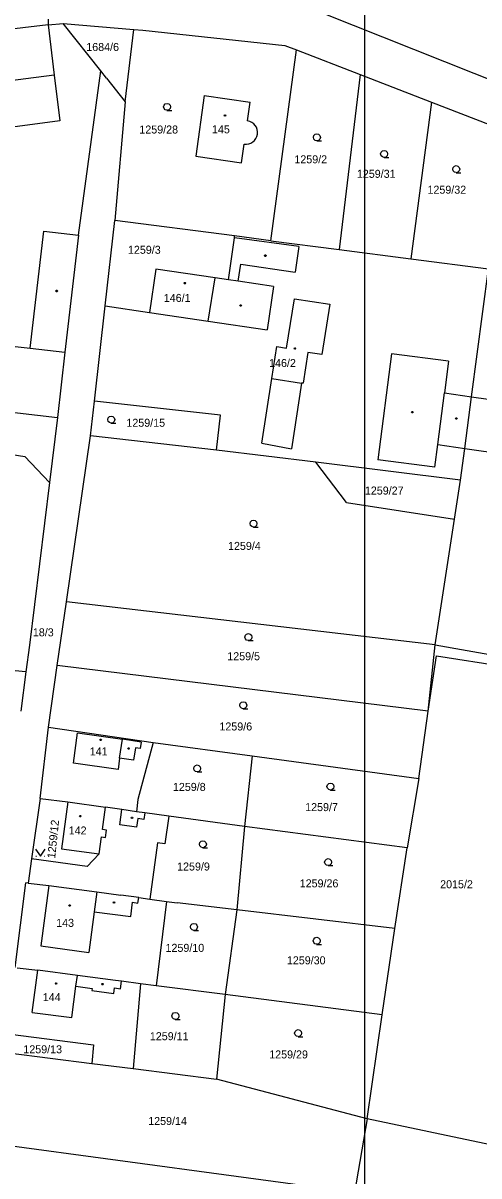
# Model space of a CAD drawing. Extents: x -802857 to -799647, y -1020285 to -1015884.
# Drawn here: x -801322.5 to -801225.7, y -1017885.2 to -1017640.2 of the extents above; entities that cross this region are included whole.
import ezdxf

# ---------------------------------------------------------------- set-up
doc = ezdxf.new("R2010")
doc.units = 0
for name, color, linetype in [('Default', 7, 'Continuous'), ('KLADY_ZMVM', 7, 'Continuous'), ('KN_HRANICE', 7, 'Continuous'), ('KN_KULTURY', 7, 'Continuous'), ('KN_PARCELY', 7, 'Continuous'), ('KN_SLUCKY', 7, 'Continuous')]:
    doc.layers.add(name, color=color, linetype=linetype)

# ---------------------------------------------------------------- blocks, each defined once
blk = doc.blocks.new('304')
at = {"layer": 'Default'}
blk.add_lwpolyline([(0, 0), (-0.38, 0.1), (-0.65, 0.37), (-0.75, 0.74), (-0.65, 1.11), (-0.38, 1.38), (-0.01, 1.48), (0.36, 1.38), (0.63, 1.11), (0.73, 0.73), (0.63, 0.35), (0.36, 0.08), (-0.02, -0.02), (0.98, -0.02)], dxfattribs=at)
blk = doc.blocks.new('314')
at = {"layer": 'Default'}
for p, q in [((-0.95, 0), (-0.85, 0)), ((0.85, 0), (0.95, 0))]:
    blk.add_line(p, q, dxfattribs=at)
blk.add_lwpolyline([(-1, 1.5), (0, 0), (1, 1.5)], dxfattribs=at)
blk = doc.blocks.new('402')
at = {"layer": 'Default'}
blk.add_lwpolyline([(0.09, 0.15), (0.18, 0), (0.09, -0.15), (-0.09, -0.15), (-0.18, 0), (-0.09, 0.15), (0.09, 0.15)], dxfattribs=at)

msp = doc.modelspace()

# ---------------------------------------------------------------- linework, layer by layer
at = {"layer": 'KLADY_ZMVM'}
msp.add_lwpolyline([(-801250, -1017000), (-801250, -1017500), (-801250, -1018000)], dxfattribs=at)
at = {"layer": 'KN_HRANICE'}
for p, q in [((-801258.97, -1017638.08), (-801218.75, -1017654.12)), ((-801317.19, -1017639.44), (-801317.18, -1017640.62)), ((-801317.18, -1017640.62), (-801313.96, -1017640.33)), ((-801317.18, -1017640.62), (-801315.88, -1017651.33)), ((-801313.96, -1017640.33), (-801298.97, -1017641.6)), ((-801306.02, -1017650.39), (-801313.96, -1017640.33)), ((-801300.81, -1017657), (-801298.97, -1017641.6)), ((-801298.97, -1017641.6), (-801297.08, -1017641.76)), ((-801297.08, -1017641.76), (-801266.9, -1017645.01)), ((-801269.88, -1017686.48), (-801264.46, -1017645.95)), ((-801266.9, -1017645.01), (-801264.46, -1017645.95)), ((-801264.46, -1017645.95), (-801250.95, -1017651.18)), ((-801310.75, -1017685.3), (-801306.02, -1017650.39)), ((-801304.78, -1017651.96), (-801306.02, -1017650.39)), ((-801250.95, -1017651.18), (-801255.36, -1017688.35)), ((-801250.95, -1017651.18), (-801235.81, -1017657.04)), ((-801315.88, -1017651.33), (-801314.72, -1017661.03)), ((-801304.78, -1017651.96), (-801300.81, -1017657)), ((-801284.03, -1017655.6), (-801285.84, -1017668.53)), ((-801284.03, -1017655.6), (-801274.3, -1017657.02)), ((-801300.81, -1017657), (-801303.02, -1017682.18)), ((-801274.86, -1017661.01), (-801274.3, -1017657.02)), ((-801235.81, -1017657.04), (-801240.18, -1017690.3)), ((-801235.81, -1017657.04), (-801220.05, -1017663.14)), ((-801314.72, -1017661.03), (-801346.31, -1017665.23)), ((-801276.11, -1017669.95), (-801275.55, -1017665.96)), ((-801285.84, -1017668.53), (-801276.11, -1017669.95)), ((-801305.07, -1017700.32), (-801303.02, -1017682.18)), ((-801277.57, -1017685.48), (-801303.02, -1017682.18)), ((-801310.75, -1017685.3), (-801313.62, -1017710.16)), ((-801278.9, -1017694.79), (-801277.62, -1017685.88)), ((-801277.62, -1017685.88), (-801277.57, -1017685.48)), ((-801269.88, -1017686.48), (-801277.57, -1017685.48)), ((-801269.88, -1017686.48), (-801255.36, -1017688.35)), ((-801255.36, -1017688.35), (-801240.18, -1017690.3)), ((-801240.18, -1017690.3), (-801223.64, -1017692.43)), ((-801294.28, -1017692.51), (-801295.64, -1017701.71)), ((-801281.73, -1017694.37), (-801294.28, -1017692.51)), ((-801227.27, -1017719.62), (-801223.64, -1017692.43)), ((-801278.9, -1017694.79), (-801281.73, -1017694.37)), ((-801266.53, -1017709.31), (-801264.9, -1017698.8)), ((-801264.9, -1017698.8), (-801257.36, -1017699.97)), ((-801257.36, -1017699.97), (-801259.03, -1017710.68)), ((-801307.35, -1017720.56), (-801305.07, -1017700.32)), ((-801305.07, -1017700.32), (-801295.64, -1017701.71)), ((-801269.68, -1017715.75), (-801268.63, -1017708.99)), ((-801268.63, -1017708.99), (-801266.53, -1017709.31)), ((-801313.62, -1017710.16), (-801315.22, -1017724.02)), ((-801262.01, -1017710.22), (-801263.03, -1017716.78)), ((-801259.03, -1017710.68), (-801262.01, -1017710.22)), ((-801271.82, -1017729.5), (-801269.68, -1017715.75)), ((-801263.35, -1017716.73), (-801265.52, -1017730.72)), ((-801263.03, -1017716.78), (-801263.35, -1017716.73)), ((-801360.4, -1017718.86), (-801315.22, -1017724.02)), ((-801228.73, -1017730.61), (-801227.27, -1017719.62)), ((-801308.18, -1017727.92), (-801307.35, -1017720.56)), ((-801280.57, -1017723.56), (-801307.35, -1017720.56)), ((-801315.22, -1017724.02), (-801316.92, -1017737.87)), ((-801281.41, -1017730.95), (-801280.57, -1017723.56)), ((-801313.28, -1017763.19), (-801308.18, -1017727.92)), ((-801281.41, -1017730.95), (-801308.18, -1017727.92)), ((-801271.82, -1017729.5), (-801265.52, -1017730.72)), ((-801330.53, -1017731.02), (-801322.14, -1017732.32)), ((-801260.34, -1017733.55), (-801281.41, -1017730.95)), ((-801229.63, -1017737.33), (-801228.73, -1017730.61)), ((-801322.14, -1017732.32), (-801316.92, -1017737.87)), ((-801253.83, -1017742.07), (-801260.34, -1017733.55)), ((-801229.63, -1017737.33), (-801260.34, -1017733.55)), ((-801316.92, -1017737.87), (-801321.16, -1017772.38)), ((-801230.91, -1017745.67), (-801229.63, -1017737.33)), ((-801253.83, -1017742.07), (-801230.91, -1017745.67)), ((-801234.99, -1017772.37), (-801230.91, -1017745.67)), ((-801315.24, -1017776.75), (-801313.28, -1017763.19)), ((-801234.99, -1017772.37), (-801313.28, -1017763.19)), ((-801321.16, -1017772.38), (-801321.89, -1017778.08)), ((-801236.48, -1017786.43), (-801234.99, -1017772.37)), ((-801234.99, -1017772.37), (-801172.15, -1017783.49)), ((-801236.48, -1017786.43), (-801234.69, -1017774.68)), ((-801234.69, -1017774.68), (-801206.04, -1017779.14)), ((-801321.89, -1017778.08), (-801333.83, -1017776.95)), ((-801321.89, -1017778.08), (-801322.97, -1017786.42)), ((-801317.13, -1017789.83), (-801315.24, -1017776.75)), ((-801236.48, -1017786.43), (-801315.24, -1017776.75)), ((-801238.47, -1017800.75), (-801236.48, -1017786.43)), ((-801318.85, -1017804.96), (-801317.13, -1017789.83)), ((-801317.13, -1017789.83), (-801294.9, -1017793.05)), ((-801294.9, -1017793.05), (-801298.1, -1017805.2)), ((-801294.9, -1017793.05), (-801273.85, -1017795.89)), ((-801273.85, -1017795.89), (-801275.49, -1017810.94)), ((-801273.85, -1017795.89), (-801238.47, -1017800.75)), ((-801238.47, -1017800.75), (-801240.97, -1017815.46)), ((-801318.85, -1017804.96), (-801320.69, -1017817.83)), ((-801318.85, -1017804.96), (-801313, -1017805.71)), ((-801298.1, -1017805.2), (-801298.41, -1017807.79)), ((-801313, -1017805.71), (-801314.37, -1017815.67)), ((-801313, -1017805.71), (-801305, -1017806.85)), ((-801301.51, -1017807.35), (-801305, -1017806.85)), ((-801298.41, -1017807.79), (-801301.51, -1017807.35)), ((-801296.65, -1017808.02), (-801298.41, -1017807.79)), ((-801291.57, -1017808.72), (-801296.65, -1017808.02)), ((-801291.57, -1017808.72), (-801292.38, -1017814.62)), ((-801275.49, -1017810.94), (-801291.57, -1017808.72)), ((-801275.49, -1017810.94), (-801277.13, -1017828.65)), ((-801240.97, -1017815.46), (-801275.49, -1017810.94)), ((-801293.96, -1017814.4), (-801295.6, -1017826.35)), ((-801292.38, -1017814.62), (-801293.96, -1017814.4)), ((-801314.37, -1017815.67), (-801306.37, -1017816.77)), ((-801306.37, -1017816.77), (-801308.92, -1017819.41)), ((-801243.53, -1017832.62), (-801240.97, -1017815.46)), ((-801320.69, -1017817.83), (-801321.42, -1017822.98)), ((-801308.92, -1017819.41), (-801320.69, -1017817.83)), ((-801324.21, -1017840.9), (-801321.92, -1017822.92)), ((-801321.42, -1017822.98), (-801321.92, -1017822.92)), ((-801321.42, -1017822.98), (-801317, -1017823.5)), ((-801317, -1017823.5), (-801306.82, -1017824.84)), ((-801306.82, -1017824.84), (-801301.75, -1017825.51)), ((-801297.95, -1017826.03), (-801301.75, -1017825.51)), ((-801297.95, -1017826.03), (-801295.6, -1017826.35)), ((-801295.6, -1017826.35), (-801292.03, -1017826.83)), ((-801292.03, -1017826.83), (-801294.26, -1017844.75)), ((-801292.03, -1017826.83), (-801289.77, -1017827.14)), ((-801277.13, -1017828.65), (-801289.77, -1017827.14)), ((-801277.13, -1017828.65), (-801279.58, -1017846.65)), ((-801243.53, -1017832.62), (-801277.13, -1017828.65)), ((-801246.26, -1017850.96), (-801243.53, -1017832.62)), ((-801323.76, -1017840.95), (-801319.39, -1017841.48)), ((-801310.96, -1017842.58), (-801319.39, -1017841.48)), ((-801302.87, -1017843.64), (-801310.96, -1017842.58)), ((-801301.57, -1017843.81), (-801302.87, -1017843.64)), ((-801297.53, -1017844.33), (-801301.57, -1017843.81)), ((-801297.53, -1017844.33), (-801299.15, -1017862.36)), ((-801294.26, -1017844.75), (-801297.53, -1017844.33)), ((-801279.58, -1017846.65), (-801294.26, -1017844.75)), ((-801279.58, -1017846.65), (-801281.41, -1017864.6)), ((-801246.26, -1017850.96), (-801279.58, -1017846.65)), ((-801249.45, -1017873.01), (-801246.26, -1017850.96)), ((-801325.19, -1017855.03), (-801307.53, -1017857.34)), ((-801325.59, -1017859.01), (-801307.91, -1017861.25)), ((-801307.53, -1017857.34), (-801307.91, -1017861.25)), ((-801307.91, -1017861.25), (-801299.15, -1017862.36)), ((-801299.15, -1017862.36), (-801281.41, -1017864.6)), ((-801249.45, -1017873.01), (-801281.41, -1017864.6)), ((-801249.45, -1017873.01), (-801252.11, -1017888.65)), ((-801223.26, -1017878.53), (-801249.45, -1017873.01)), ((-801252.11, -1017888.65), (-801327.56, -1017878.51))]:
    msp.add_line(p, q, dxfattribs=at)
msp.add_arc((-801275.2, -1017663.49), 2.5, 262.0645, 82.0644, dxfattribs=at)
at = {"layer": 'KN_SLUCKY'}
for p, q in [((-801317.18, -1017640.62), (-801334.53, -1017642.7)), ((-801315.88, -1017651.33), (-801346.88, -1017655.22)), ((-801320.96, -1017709.32), (-801318.12, -1017684.46)), ((-801318.12, -1017684.46), (-801310.75, -1017685.3)), ((-801263.92, -1017687.68), (-801277.62, -1017685.88)), ((-801263.92, -1017687.68), (-801264.71, -1017693.15)), ((-801276.81, -1017695.1), (-801276.28, -1017691.44)), ((-801276.28, -1017691.44), (-801264.71, -1017693.15)), ((-801283.17, -1017703.56), (-801281.73, -1017694.37)), ((-801276.81, -1017695.1), (-801278.9, -1017694.79)), ((-801269.34, -1017696.2), (-801276.81, -1017695.1)), ((-801269.34, -1017696.2), (-801270.7, -1017705.4)), ((-801295.64, -1017701.71), (-801283.17, -1017703.56)), ((-801283.17, -1017703.56), (-801270.7, -1017705.4)), ((-801335.42, -1017707.67), (-801320.96, -1017709.32)), ((-801320.96, -1017709.32), (-801313.62, -1017710.16)), ((-801244.25, -1017710.49), (-801247.15, -1017733)), ((-801232.15, -1017712.05), (-801244.25, -1017710.49)), ((-801232.15, -1017712.05), (-801233.02, -1017718.8)), ((-801269.68, -1017715.75), (-801263.35, -1017716.73)), ((-801234.44, -1017729.8), (-801233.02, -1017718.8)), ((-801233.02, -1017718.8), (-801227.27, -1017719.62)), ((-801227.27, -1017719.62), (-801204.41, -1017722.86)), ((-801235.05, -1017734.56), (-801234.44, -1017729.8)), ((-801234.44, -1017729.8), (-801228.73, -1017730.61)), ((-801228.73, -1017730.61), (-801206.81, -1017733.72)), ((-801235.05, -1017734.56), (-801247.15, -1017733)), ((-801311.81, -1017797.47), (-801310.92, -1017791.04)), ((-801310.92, -1017791.04), (-801301.41, -1017792.41)), ((-801301.99, -1017796.42), (-801301.41, -1017792.41)), ((-801297.4, -1017792.99), (-801301.41, -1017792.41)), ((-801297.4, -1017792.99), (-801297.6, -1017794.37)), ((-801298.64, -1017794.22), (-801299.02, -1017796.85)), ((-801297.6, -1017794.37), (-801298.64, -1017794.22)), ((-801302.34, -1017798.84), (-801311.81, -1017797.47)), ((-801301.99, -1017796.42), (-801302.34, -1017798.84)), ((-801299.02, -1017796.85), (-801301.99, -1017796.42)), ((-801305.65, -1017811.57), (-801305, -1017806.85)), ((-801301.96, -1017810.55), (-801301.51, -1017807.35)), ((-801298.14, -1017809.22), (-801298.4, -1017811.06)), ((-801296.85, -1017809.41), (-801298.14, -1017809.22)), ((-801296.65, -1017808.02), (-801296.85, -1017809.41)), ((-801304.76, -1017811.69), (-801305.65, -1017811.57)), ((-801304.98, -1017813.28), (-801304.76, -1017811.69)), ((-801298.4, -1017811.06), (-801301.96, -1017810.55)), ((-801306.37, -1017816.77), (-801305.87, -1017813.15)), ((-801305.87, -1017813.15), (-801304.98, -1017813.28)), ((-801317, -1017823.5), (-801318.7, -1017836.28)), ((-801306.82, -1017824.84), (-801307.38, -1017829.03)), ((-801299.65, -1017830.06), (-801299.25, -1017827.03)), ((-801299.25, -1017827.03), (-801298.11, -1017827.19)), ((-801298.11, -1017827.19), (-801297.95, -1017826.03)), ((-801307.38, -1017829.03), (-801308.53, -1017837.68)), ((-801307.38, -1017829.03), (-801299.65, -1017830.06)), ((-801318.7, -1017836.28), (-801308.53, -1017837.68)), ((-801320.6, -1017850.42), (-801319.39, -1017841.48)), ((-801311.27, -1017844.87), (-801310.96, -1017842.58)), ((-801301.79, -1017845.4), (-801301.57, -1017843.81)), ((-801312.17, -1017851.52), (-801311.27, -1017844.87)), ((-801311.27, -1017844.87), (-801307.84, -1017845.34)), ((-801307.84, -1017845.34), (-801307.9, -1017845.78)), ((-801307.9, -1017845.78), (-801303.25, -1017846.42)), ((-801303.25, -1017846.42), (-801303.09, -1017845.22)), ((-801303.09, -1017845.22), (-801301.79, -1017845.4)), ((-801320.6, -1017850.42), (-801312.17, -1017851.52))]:
    msp.add_line(p, q, dxfattribs=at)

# ---------------------------------------------------------------- block references
at = {"layer": 'KN_KULTURY'}
for name, p in [('304', (-801291.92, -1017658.78)), ('402', (-801279.61, -1017659.89)), ('304', (-801260.1, -1017665.26)), ('304', (-801245.82, -1017668.79)), ('304', (-801230.52, -1017672.02)), ('402', (-801271.07, -1017689.66)), ('402', (-801315.35, -1017697.17)), ('402', (-801288.15, -1017695.53)), ('402', (-801276.28, -1017700.24)), ('402', (-801264.78, -1017709.37)), ('304', (-801303.77, -1017725.23)), ('402', (-801239.85, -1017722.89)), ('402', (-801230.51, -1017724.25)), ('304', (-801273.56, -1017747.32)), ('304', (-801274.65, -1017771.42)), ('304', (-801275.73, -1017785.9)), ('402', (-801306.02, -1017792.52)), ('402', (-801300.1, -1017794.38)), ('304', (-801285.52, -1017799.33)), ('304', (-801257.22, -1017803.18)), ('402', (-801310.37, -1017808.73)), ('402', (-801299.38, -1017809.08)), ('304', (-801284.3, -1017815.43)), ('314', (-801318.83, -1017817.23)), ('304', (-801257.72, -1017819.23)), ('402', (-801303.19, -1017827.05)), ('402', (-801312.59, -1017827.71)), ('304', (-801286.21, -1017833)), ('304', (-801260.14, -1017835.95)), ('402', (-801315.48, -1017844.29)), ('402', (-801305.63, -1017844.4)), ('304', (-801290.15, -1017851.92)), ('304', (-801264.08, -1017855.57))]:
    msp.add_blockref(name, p, dxfattribs=at)

# ---------------------------------------------------------------- texts
at = {"layer": 'KN_PARCELY'}
for s, p in [('1684/6', (-801309.08, -1017646.18)), ('1259/28', (-801297.81, -1017663.71)), ('145', (-801282.39, -1017663.67)), ('1259/2', (-801264.89, -1017670.04)), ('1259/31', (-801251.62, -1017673.12)), ('1259/32', (-801236.63, -1017676.5)), ('1259/3', (-801300.23, -1017689.26)), ('146/1', (-801292.62, -1017699.49)), ('146/2', (-801270.26, -1017713.32)), ('1259/15', (-801300.56, -1017726.01)), ('1259/27', (-801249.92, -1017740.41)), ('1259/4', (-801278.98, -1017752.17)), ('18/3', (-801320.42, -1017770.53)), ('1259/5', (-801279.14, -1017775.61)), ('1259/6', (-801280.81, -1017790.53)), ('141', (-801308.34, -1017795.82)), ('1259/8', (-801290.68, -1017803.37)), ('1259/7', (-801262.6, -1017807.66)), ('142', (-801312.81, -1017812.63)), ('1259/9', (-801289.79, -1017820.28)), ('1259/26', (-801263.76, -1017823.86)), ('2015/2', (-801233.94, -1017824.05)), ('143', (-801315.47, -1017832.25)), ('1259/10', (-801292.25, -1017837.56)), ('1259/30', (-801266.48, -1017840.21)), ('144', (-801318.31, -1017848.03)), ('1259/11', (-801295.58, -1017856.33)), ('1259/13', (-801322.44, -1017859.11)), ('1259/29', (-801270.23, -1017860.2)), ('1259/14', (-801295.93, -1017874.35))]:
    msp.add_text(s, height=1.7, dxfattribs=at).set_placement(p)
msp.add_text('1259/12', height=1.7, rotation=84.053, dxfattribs=at).set_placement((-801315.69, -1017817.77))

doc.saveas('drawing.dxf')
